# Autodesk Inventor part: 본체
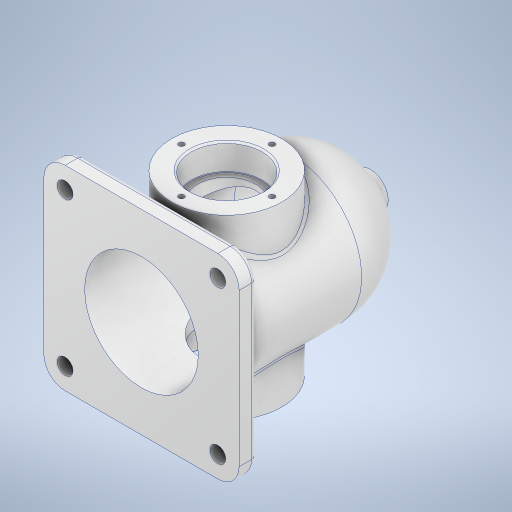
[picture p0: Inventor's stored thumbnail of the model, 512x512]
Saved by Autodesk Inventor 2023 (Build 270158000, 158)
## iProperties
Created: 2025-04
Part Number: 본체
Material: 알루미늄 6061
Document SubType Name: Modeling
Designer: ADMIN_PC
Density: 2.7 g/cm^3
Appearance: 알루미늄 - 평지
Mass: 865.906 g
Surface Area: 800.755 cm^2
Volume: 320.706 cm^3
Author: ADMIN_PC
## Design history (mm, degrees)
sketch "스케치1"
  geometry: L1 (-55, -55)-(55, -55); L2 (55, -55)-(55, 55); L3 (55, 55)-(-55, 55); L4 (-55, 55)-(-55, -55); L5 (-55, -55)-(55, 55); L6 (55, -55)-(-55, 55); 1 further point
  constraints: 12 end point, 2 midpoint, 2 parallel, 1 horizontal, 1 perpendicular
  dimensions: "d0" = 110 distance of L2.end L3.end; "d1" = 110 distance of L1.end L2.end
extrude "돌출1" new body sketch "스케치1" distance "d2" = 10; taper "d3" = 0 deg
fillet "모깎기1" dims "d4" = 12
sketch "스케치2"
  geometry: C1 r 40 at (0, 0); 1 further point
  constraints: 1 centre point, 1 coincident
  dimensions: "d5" = 80 diameter of C1
extrude "돌출2" join sketch "스케치2" distance "d6" = 74; taper "d7" = 0 deg
sketch "스케치3"
  geometry: L1 (-40, -74)-(40, -74) reference; L2 (0, -138.8)-(0, 34.8) reference; A1 r 40 centre (0, -74) between (-40, -74) and (0, -114); 2 further points
  constraints: 2 end point, 2 point on circle, 1 centre point, 1 midpoint, 1 point on line
revolve "회전1" sketch "스케치3" stored, may be unused: angle "d9" = 90 deg
sketch "스케치4"
  geometry: C1 r 32 at (0, 0); 1 further point
  constraints: 1 centre point, 1 coincident
  dimensions: "d10" = 64 diameter of C1
extrude "돌출3" cut sketch "스케치4" distance "d11" = 84; taper "d12" = 0 deg
sketch "스케치5"
  geometry: L1 (-32, -74)-(32, -74) reference; L2 (0, -138.8)-(0, 34.8) reference; A1 r 32 centre (0, -74) between (-32, -74) and (0, -106); 2 further points
  constraints: 2 point on circle, 1 centre point, 1 end point, 1 midpoint, 1 point on line
revolve "회전2" sketch "스케치5" stored, may be unused: angle "d13" = 90 deg
node "작업 평면2"
sketch "스케치6"
  geometry: L1 (-43, 10)-(43, 10) reference; L2 (0, 10)-(0, -38); C1 r 31 at (0, -38); 1 further point
  constraints: 2 end point, 1 centre point, 1 coincident, 1 midpoint, 1 vertical
  dimensions: "d15" = 48 distance of L2.start L2.end; "d16" = 62 diameter of C1
extrude "돌출4" join sketch "스케치6" stored distance "d17" = 84; taper "d18" = 0 deg
sketch "스케치7"
  geometry: C1 r 20 at (0, 0); 1 further point
  constraints: 1 centre point
  dimensions: "d19" = 40 diameter of C1
extrude "돌출5" cut sketch "스케치7" distance "d20" = 15; taper "d21" = 0 deg
sketch "스케치8"
  geometry: C1 r 16.5 at (0, 0); 1 further point
  constraints: 1 centre point
  dimensions: "d22" = 33 diameter of C1
extrude "돌출6" cut sketch "스케치8" extent not by distance; stored distance "d23" = 0; taper "d24" = 0 deg
sketch "스케치9"
  geometry: L1 (-43, -43)-(43, -43); L2 (43, -43)-(43, 43); L3 (43, 43)-(-43, 43); L4 (-43, 43)-(-43, -43); L5 (-43, -43)-(43, 43); L6 (43, -43)-(-43, 43); 5 further points
  constraints: 12 end point, 4 coincident, 2 midpoint, 2 parallel, 1 horizontal, 1 perpendicular
  dimensions: "d25" = 86 distance of L2.end L3.end; "d26" = 86 distance of L1.end L2.end
hole "구멍1" sketch "스케치9" at (-43, 43), (-43, -43), (43, -43), (43, 43) diameter "d27" = 9; stored, may be unused: countersink angle "d31" = 90 deg, drill point angle "d33" = 0 deg; dims "d28" = 12, "d29" = 4, "d30" = 2, "d32" = 17.1
sketch "스케치10" dims "d34" = 51
  geometry: L1 (0, 100.8)-(0, -72.8) reference; 3 further points
  constraints: 1 point on line, 1 vertical alignment, 2 other
hole "구멍2" sketch "스케치10" at (0, 25.5) diameter "d35" = 3.242; stored, may be unused: countersink angle "d39" = 90 deg, drill point angle "d41" = 118 deg; dims "d36" = 8, "d37" = 4, "d38" = 2, "d40" = 10
node "작업 평면3"
sketch "스케치11"
  geometry: C1 r 10 at (0, 0); 1 further point
  constraints: 1 centre point, 1 coincident
  dimensions: "d46" = 20 diameter of C1
extrude "돌출7" join sketch "스케치11" stored distance "d47" = 10; taper "d48" = 0 deg
sketch "스케치12"
  geometry: 2 further points
  constraints: 1 coincident
hole "구멍3" sketch "스케치12" at (0, 0) diameter "d49" = 5.1881; stored, may be unused: countersink angle "d53" = 90 deg, drill point angle "d55" = 0 deg; dims "d50" = 14, "d51" = 4, "d52" = 2, "d54" = 16
chamfer "모따기1" distance "d56" = 1; stored, may be unused: second distance "d57" = 2, angle "d58" = 45 deg
fillet "모깎기2" dims "d59" = 0.3
fillet "모깎기3" dims "d60" = 3
fillet "모깎기4" dims "d61" = 3
node "작업 평면4"
sketch "스케치13"
  geometry: L1 (-43, 10)-(43, 10) reference; L2 (-50, -7)-(-50, -69) reference; 2 further points
  constraints: 1 other
  dimensions: "d63" = 30 distance from line of L1 point (0, -20); "d64" = 50 distance from line of L2 point (0, -20)
feature "엠보싱1" sketch "스케치13" dims "d0" = 110, "d1" = 110, "d65" = 0.5, "d66" = 0
fillet "모깎기5" dims "d67" = 3
fillet "모깎기6" dims "d68" = 3
node "솔리드1"
mirror "미러1"
mirror "미러2"
pattern_circular "원형 패턴1" dims angle "d43" = 360 deg
mirror "미러3"
feature "A9D066F2-1C7D-4E18-AEED-F7BC21143FA4" dims "d27" = 9, "d28" = 12, "d29" = 4, "d30" = 2, "d31" = 90 deg, "d32" = 17.1, "d33" = 0
other parameters: "d45" = -119
